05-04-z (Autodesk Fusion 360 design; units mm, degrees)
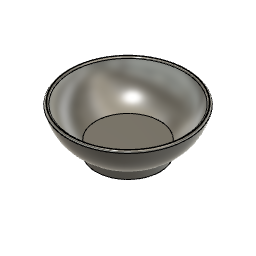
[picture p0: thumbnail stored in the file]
sketch "スケッチ1" plane through (0, 0, 0) normal (0, 0, 1) x axis (1, 0, 0)
  line L1 (-7, -2) -> (-8, -2)
  line L2 (-7, 0) -> (-7, -2)
  line L3 (-8, 0) -> (-7, 0)
  line L4 (-8, -2) -> (-8, 0)
  line L5 (0, 22.5) -> (0, 1.75)
  point P1 (0, 0)
  point P4 (-7, 0)
  point P2 (-8, -2)
  point P3 (-7, -2)
  point P5 (-8, 0)
  horizontal L1
  vertical L2
  horizontal L3
  vertical L4
  horizontal P1 P4
  dimension "d1" distance P2 P3 = 1
  dimension "d2" distance P2 P5 = 2
  dimension "d3" = 16
revolve "回転1" sketch "スケッチ1" AlongAngle 360
sketch "スケッチ2" plane through (0, 0, 0) normal (0, 0, 1) x axis (1, 0, 0)
  line L1 (-8, 0) -> (0, 0)
  line L2 (-8, 1) -> (-8, 0)
  line L3 (0, 1) -> (-8, 1)
  line L4 (0, 0) -> (0, 1)
  line L5 (-8, -2) -> (-8, 0)
  line L6 (8, 0) -> (8, -2)
  point P1 (0, 0)
  point P2 (0, 0)
  point P3 (-8, 0)
  point P4 (-8, 1)
  horizontal L1
  vertical L2
  horizontal L3
  vertical L4
  coincident P1 P2
  collinear L2 L5
  dimension "d5" distance P3 P4 = 1
revolve "回転2" sketch "スケッチ2" AlongAngle 360
sketch "スケッチ3" plane through (0, 0, 0) normal (0, 0, 1) x axis (1, 0, 0)
  line L1 (-14.0784, 9) -> (-15, 9)
  line L2 (-8, 0) -> (-8, 1)
  line L3 (-8, -2) -> (-8, 1)
  line L4 (8, 1) -> (8, -2)
  line L5 (0, 22.5) -> (0, 1.75)
  arc A1 centre (-3.1649, 10.9828) radius 11.0921 clockwise from (-8, 1) to (-14.0784, 9)
  arc A2 centre (-3.1649, 10.9828) radius 12 clockwise from (-8, 0) to (-15, 9)
  point P3 (-8, 1)
  point P8 (-8, 1)
  point P1 (0, 0)
  point P6 (-8, 0)
  vertical L2
  horizontal L1
  concentric A1 A2
  coincident P3 P8
  horizontal P1 P6
  dimension "d7" distance P1 L1 = 9
  dimension "d8" radius A2 = 12
  dimension "d9" = 30
revolve "回転3" sketch "スケッチ3" AlongAngle 360
fillet "フィレット" radius 0.4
